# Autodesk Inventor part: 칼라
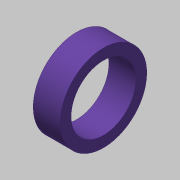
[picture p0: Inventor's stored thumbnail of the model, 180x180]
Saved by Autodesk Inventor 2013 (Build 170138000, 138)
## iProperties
Created: 2020-04
Part Number: 칼라
Material: 강철, 연강
Document SubType Name: Modeling
Designer: mduedu
Density: 1 g/cm^3
Author: mduedu
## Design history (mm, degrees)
sketch "스케치1"
  geometry: C1 r 8 at (0, 0); C2 r 6 at (0, 0); 1 further point
  constraints: 2 centre point, 2 coincident
  dimensions: "d0" = 16 diameter of C1; "d1" = 12 diameter of C2
extrude "돌출1" new body sketch "스케치1" distance "d2" = 5; taper "d3" = 0 deg
node "솔리드1"
